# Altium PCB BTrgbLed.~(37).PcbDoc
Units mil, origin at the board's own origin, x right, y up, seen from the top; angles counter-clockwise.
Board outline 3886.28 x 3884.79 mil, 2 copper layers (Top Layer, Bottom Layer); 13 components, 12 nets, 62 pads, 7 vias.
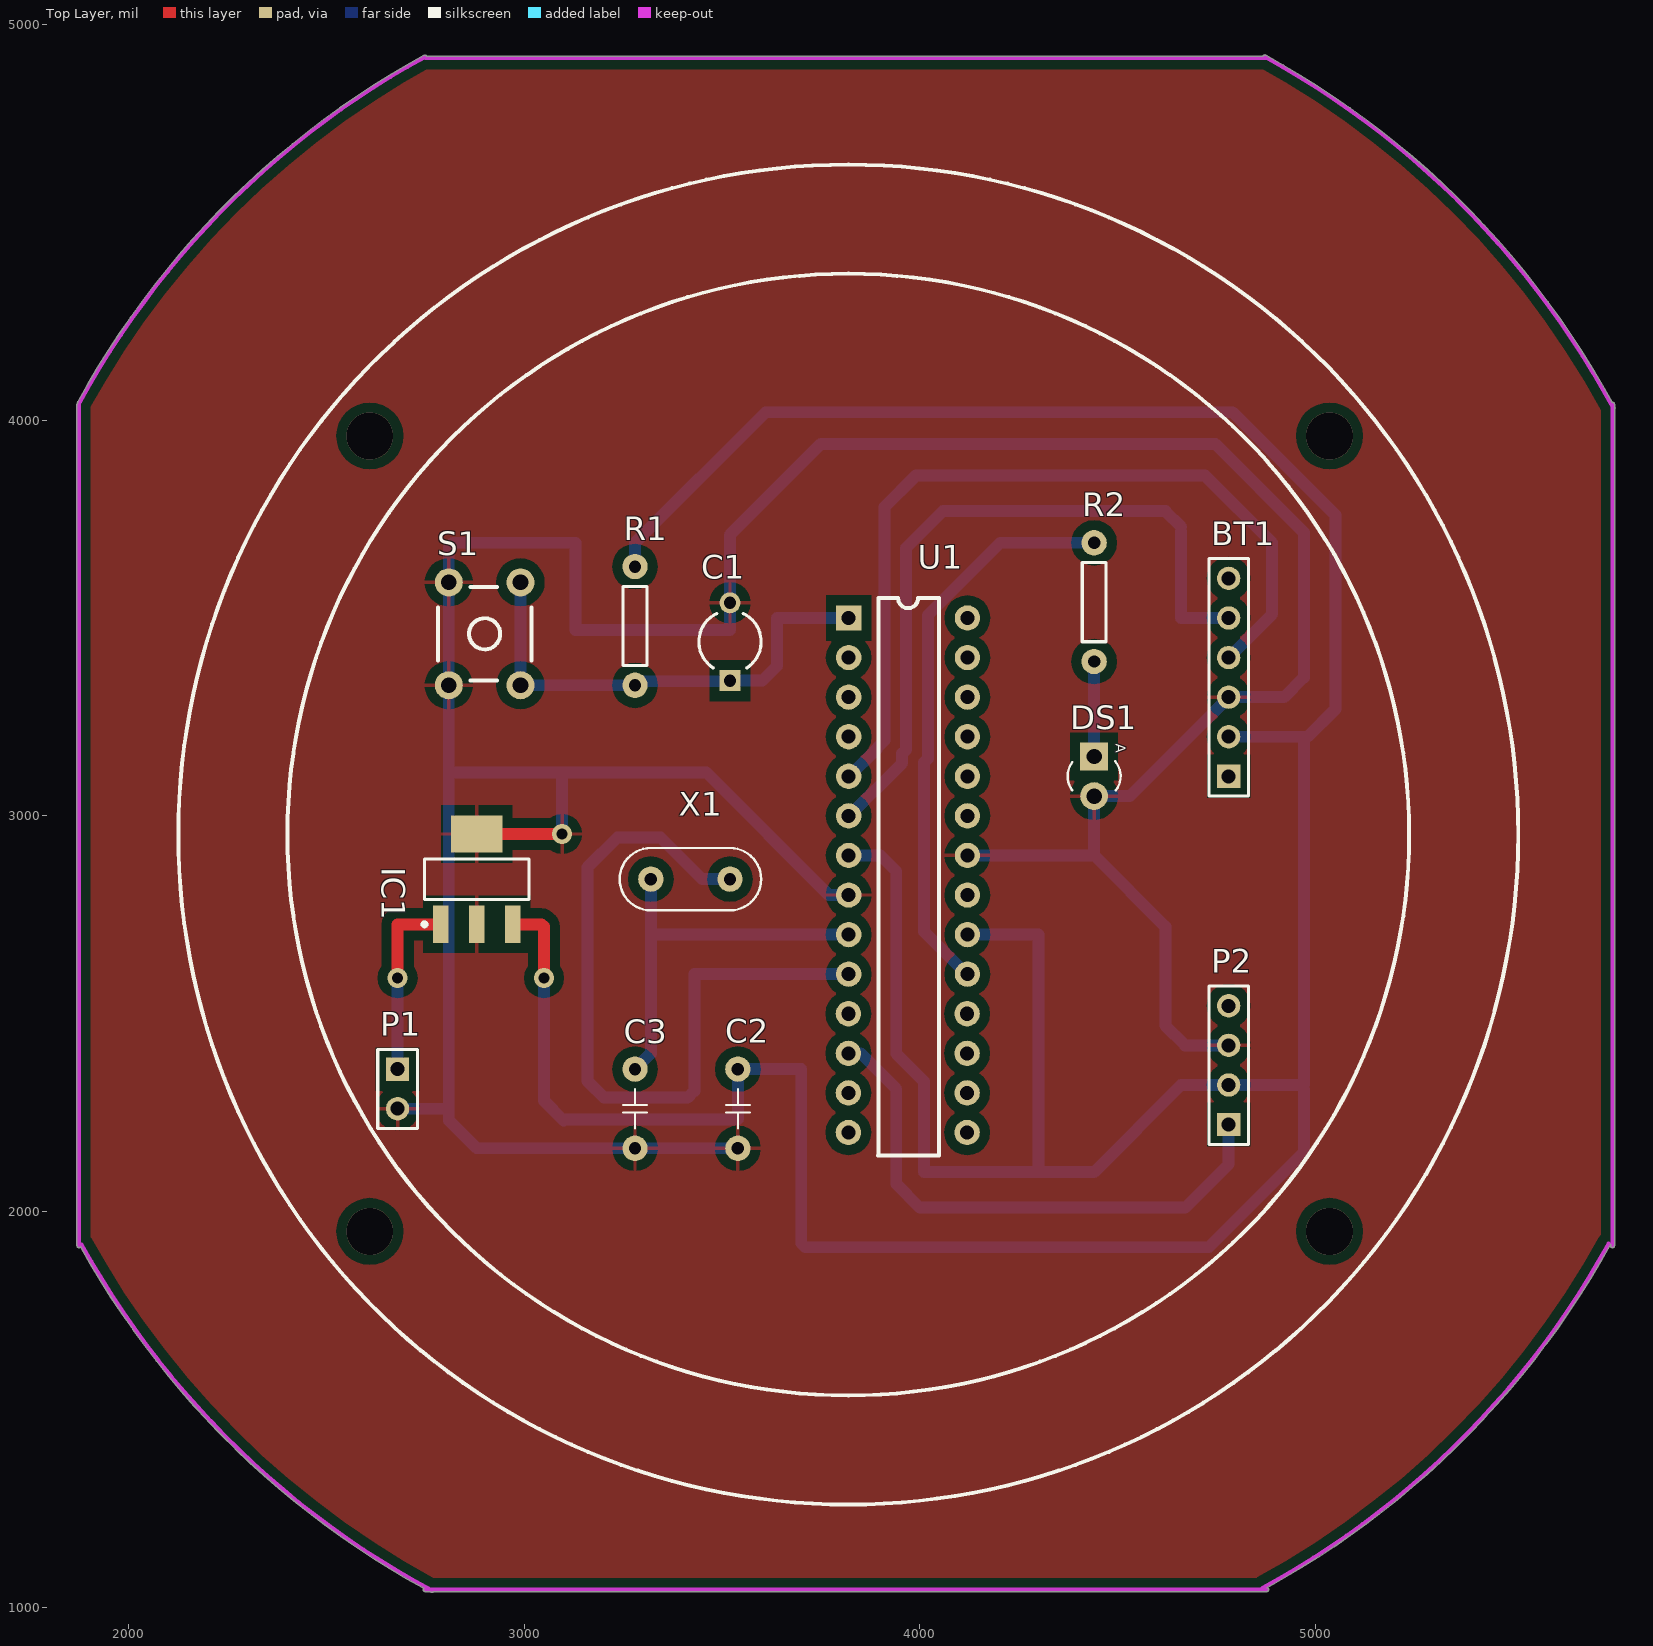
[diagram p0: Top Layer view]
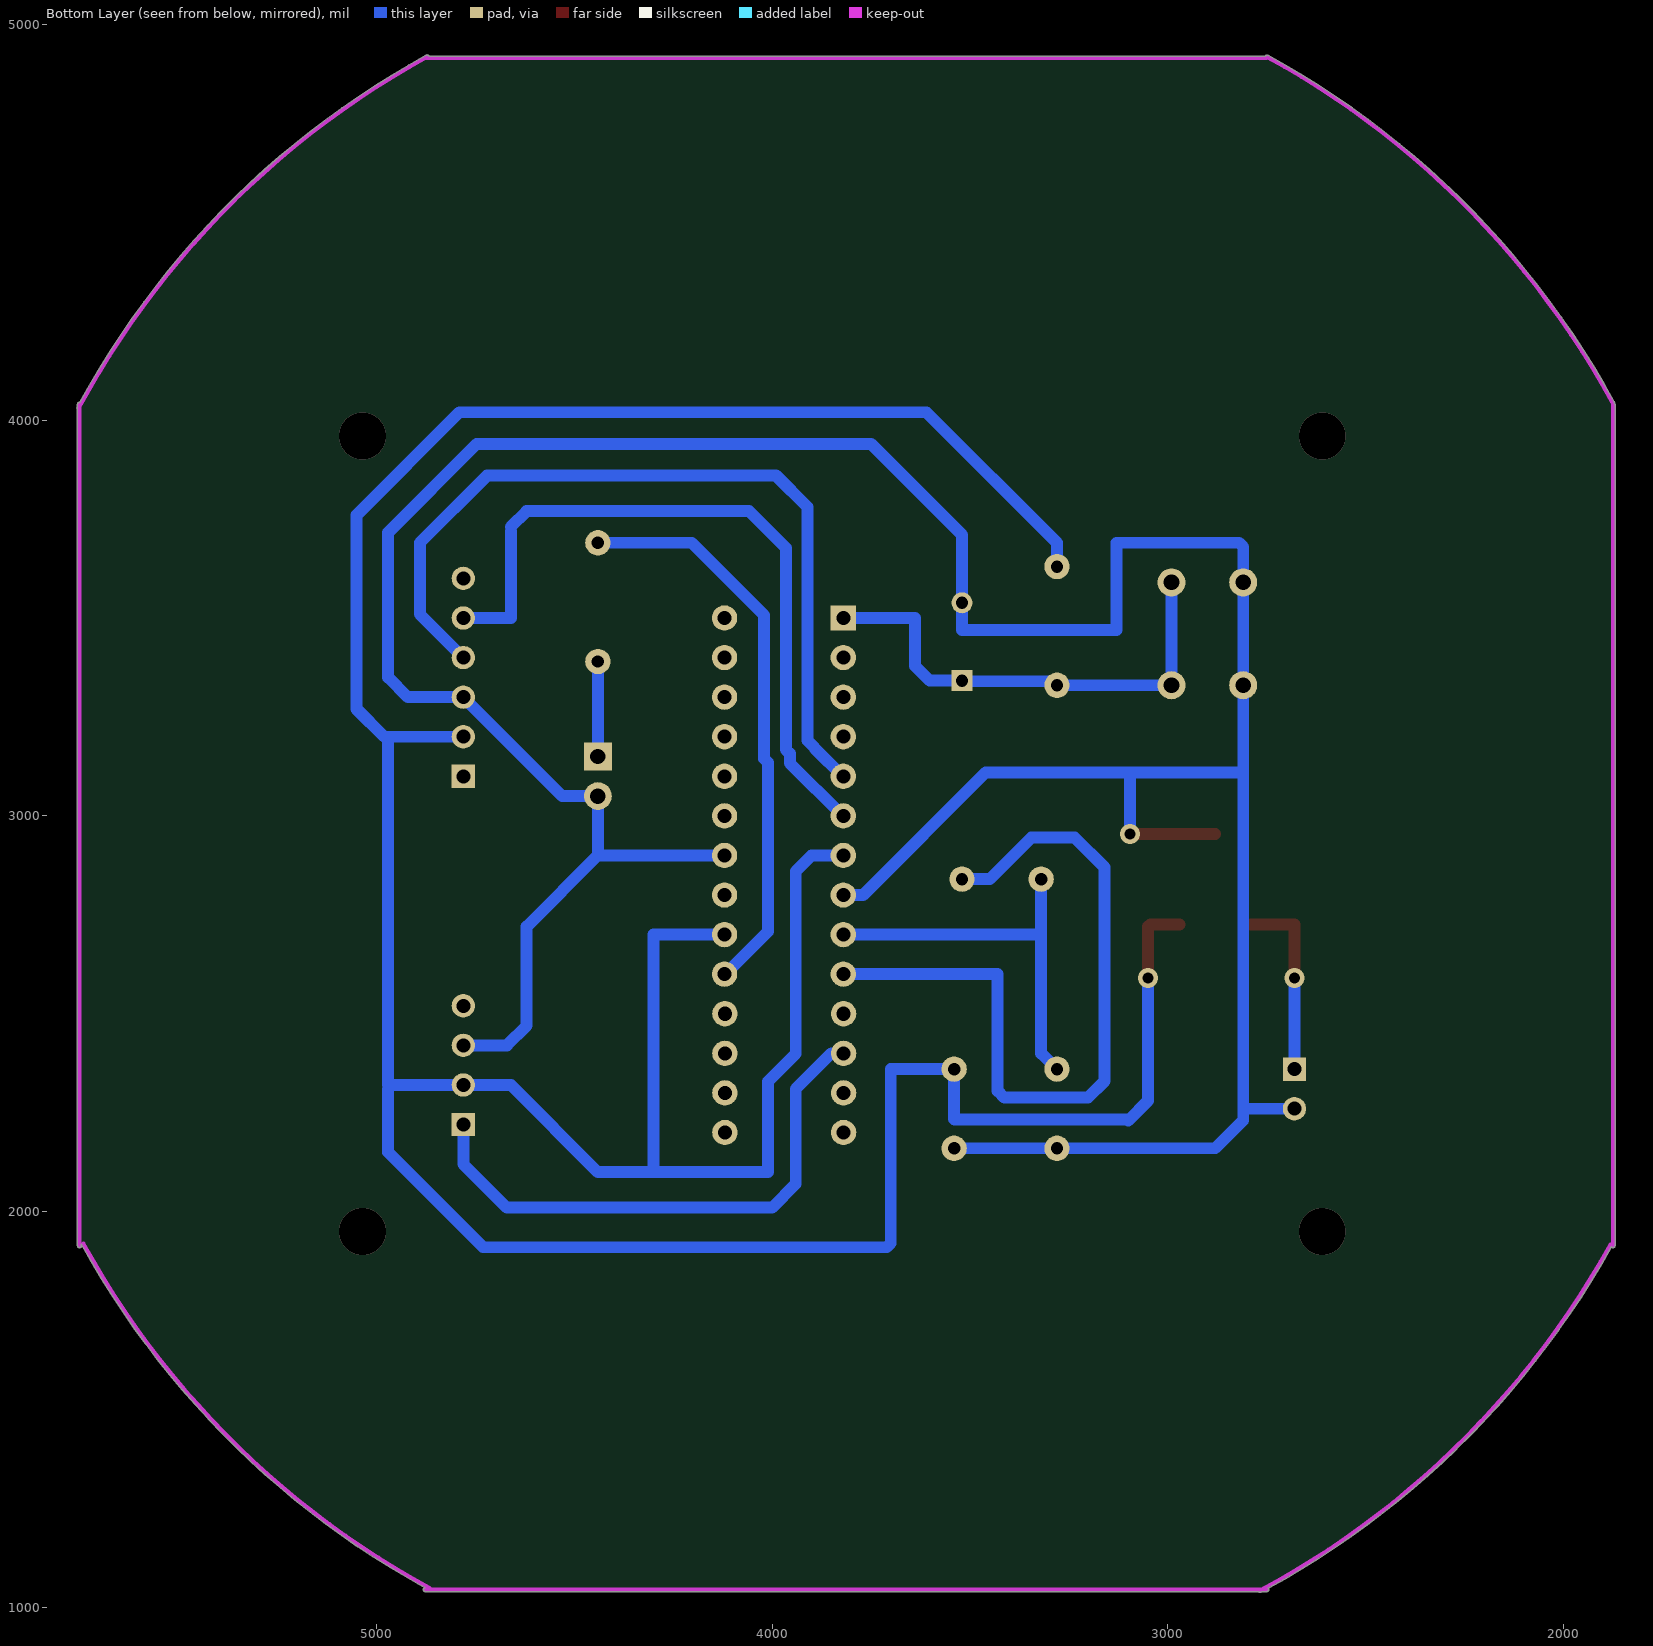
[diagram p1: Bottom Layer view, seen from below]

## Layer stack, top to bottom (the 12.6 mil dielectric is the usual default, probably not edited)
Top Layer: signal copper 1.4
Dielectric: dielectric 12.6, FR-4, Dk 4.8
Bottom Layer: signal copper 1.4

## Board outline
2750,1039.98 2761.53,1039.98 ccw(c3810.28,2985) 2764.5,1038.38 ccw(c2766.88,1042.8) 2771.03,1039.98 4875.98,1039.98 ccw(c4875.98,1045) 4881,1045 ccw(c4875.98,1045) 4877.16,1049.88 ccw(c3810.28,2985) 5744.74,1916.92 ccw(c5740.35,1919.34) 5744.98,1917.43 5744.98,1914.02 ccw(c5750,1914.02) 5755.02,1914.02 5755.02,4027.36 ccw(c5751.25,4030.67) 5756.26,4030.67 ccw(c5751.25,4030.67) 5755.66,4033.05 ccw(c3810.28,2985) 5755.02,4034.26 5755.02,4040 ccw(c5750,4040) 5749.21,4044.95 ccw(c3810.28,2985) 4873.82,4921.96 ccw(c4871.41,4917.56) 4867.03,4920.02 2752.96,4920.02 ccw(c2748.72,4917.33) 2746.3,4921.73 ccw(c3810.28,2985) 1872.41,4046.9 ccw(c1876.81,4044.49) 1871.83,4043.89 ccw(c1875,4040) 1869.98,4040 1869.98,1914.02 ccw(c1875,1914.02) 1879.06,1911.07 ccw(c3810.28,2985) 2746.23,1048.31 ccw(c2750,1045)

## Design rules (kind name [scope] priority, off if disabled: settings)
Clearance 舖銅安全間距 [All] p1: gap=25
Clearance [All] p2: gap=10
PolygonConnect [All] p1: connectstyle=Relief reliefconductorwidth=10 reliefentries=4 polygonreliefangle="90 Angle"
RoutingLayers [All] p1: top layer_v5=FALSE bottom layer_v5=TRUE
RoutingVias [All] p1: holewidth=28 width=50 viastyle="Through Hole" minholewidth=28 minwidth=50 maxholewidth=28 maxwidth=50
SilkscreenOverComponentPads [All] p1: minsilkscreentomaskgap=10
SolderMaskExpansion [All] p1: expansion=4
Width [All] p1: maxlimit=40 minlimit=20 preferedwidth=30
26 further rules are at their usual default settings.

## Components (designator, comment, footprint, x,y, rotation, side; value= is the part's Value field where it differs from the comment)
BT1 "Bluetooth" Bluetooth 4780,3100 r90 top
C1 "47uF" CAPR5-4X5 3520,3440 r90 top
C2 "22pF" C200 3540,2260 r0 top
C3 "22pF" C200 3280,2260 r180 top
DS1 "TX-LED" LED-3mm_G 4440,3100 r270 top
IC1 "AM1117-5V" SOT-223 2880,2840 r90 top
P1 "12V" HDR1X2 2680,2360 r270 top
P2 "環形LED燈" HDR1X4 4780,2220 r90 top
R1 "10k" AXIAL-0.3 3280,3480 r270 top
R2 "220" AXIAL-0.3 4440,3540 r90 top
S1 "SW-PB" TACK6 2900,3460 r90 top
U1 "ATmega328" DIP-28 3820,3500 r270 top
X1 "16MHz" XTAL4-8 3420,2840 r0 top

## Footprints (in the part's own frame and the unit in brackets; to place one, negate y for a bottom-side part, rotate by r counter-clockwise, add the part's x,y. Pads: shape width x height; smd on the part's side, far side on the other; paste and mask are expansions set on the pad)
AXIAL-0.3 [mil] "0.3\" Resistor; 2 Leads"
  round 64 hole 31.5: 1(-150,0) 2(150,0)
  silkscreen extent -100,-30 100,30, body extent -161,-39 165,39, height 86
Bluetooth [mm]
  rect 1.5x1.5 hole 0.9: 1(0,0)
  round 1.5 hole 0.9: 2(2.54,0) 3(5.08,0) 4(7.62,0) 5(10.16,0) 6(12.7,0)
  silkscreen extent -1.27,-1.27 13.97,1.27, body extent -1.25,-1.3 13.97,1.28, height 11
C200 [mil] "塑膠電容器"
  round 64 hole 31.5: 1(0,100) 2(0,-100)
  silkscreen extent -30,-50 30,50, body extent -41,-136 39,135, height 354
CAPR5-4X5 [mm] "Capacitor; 2 Leads"
  rect 1.35x1.35 hole 0.8: 1(-2.5,0)
  round 1.35 hole 0.8: 2(2.5,0)
  silkscreen extent -1.69,-2 1.82,2
DIP-28 [mil]
  rect 64x64 hole 35.43: 1(0,0)
  round 64 hole 35.43: 2(100,0) 3(200,0) 4(300,0) 5(400,0) 6(500,0) 7(600,0) 8(700,0) 9(800,0) 10(900,0) 11(1000,-0.79) 12(1100,-0.79) 13(1200,-0.79) 14(1300,-0.79) 15(1300,299.21) 16(1200,299.21) 17(1100,299.21) 18(1000,299.21) 19(900,300) 20(800,300) 21(700,300) 22(600,300) 23(500,300) 24(400,300) 25(300,300) 26(200,300) 27(100,300) 28(0,300)
  silkscreen extent -50,74 1358,228, body extent -53,-5 1358,304, height 209
HDR1X2 [mm] "Connector; Header; 2 Position"
  rect 1.5x1.5 hole 0.9: 1(0,0)
  round 1.5 hole 0.9: 2(2.54,0)
  silkscreen extent -1.27,-1.27 3.81,1.27
HDR1X4 [mm] "Connector; Header; 4 Position"
  rect 1.5x1.5 hole 0.9: 1(0,0)
  round 1.5 hole 0.9: 2(2.54,0) 3(5.08,0) 4(7.62,0)
  silkscreen extent -1.27,-1.27 8.89,1.27
LED-3mm_G [mil] "3mm LED_Green"
  rect 70x70 hole 39: 1(-50,0)
  round 70 hole 39: 2(50,0)
  silkscreen extent -38,-67 35,67, body extent -66,-68 67,66, height 181
SOT-223 [mm] "SOT223, 4-Leads, Body 6.7x7.3mm (max), Pitch 2.30mm, IPC Medium Density"
  rect 2.4x1 smd: 1(-2.9,2.3) 2(-2.9,0) 3(-2.9,-2.3)
  rect 2.4x3.3 smd: 2(2.9,0)
  silkscreen extent -3.02,-3.35 1.3,3.47, body extent -1.86,-3.35 1.86,3.35, height 1.8
TACK6 [mm]
  round 1.8 hole 1: 1(-3.3,2.3) 1(3.3,2.3) 2(-3.3,-2.3) 2(3.3,-2.3)
  silkscreen extent -3,-3 3,3, body extent -3,-3.01 3.08,3.04, height 8
XTAL4-8 [mil]
  round 64 hole 31.5: 1(-100,0) 2(100,0)
  silkscreen extent -179,-79 179,79, body extent -178,-80 192,79, height 157

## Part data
C1: library part "Cap Pol1", "Polarized Capacitor (Radial)"
C2 C3: library part Cap, "Capacitor"
DS1: library part LED, "Typical INFRARED GaAs LED"
IC1: library part AM1117
P1: library part "Header 2", "Header, 2-Pin"
P2: library part "Header 4", "Header, 4-Pin"
R1 R2: library part Res, "Resistor"
S1: "Switch"
U1: "Arduino"
X1: library part XTAL, "Crystal Oscillator"

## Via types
v1: diameter 118.11, hole 118.11, Top Layer to Bottom Layer, 4 vias
v2: diameter 50, hole 28, Top Layer to Bottom Layer, 3 vias

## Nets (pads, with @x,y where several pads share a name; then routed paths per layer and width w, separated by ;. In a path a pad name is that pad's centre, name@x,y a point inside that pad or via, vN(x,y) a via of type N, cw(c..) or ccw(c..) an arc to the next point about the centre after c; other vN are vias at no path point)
DI: P2.1 U1.12 | length 1408.5
  Bottom Layer w30: U1.12 3850,2400 3940,2310 3940,2070 4000,2010 4670,2010 4780,2120 P2.1
DO: P2.4
GND: BT1.3 C1.2 C2.2 C3.1 DS1.2 IC1.2 P1.2 P2.3 S1.1 U1.8 U1.22 | length 8812.8
  Top Layer w30: IC1.2@2880,2954.17 v2(3095.83,2954.17)
  Bottom Layer w30: P1.2 2804.45,2260 ; S1.1@2809.45,3580.49 2809.45,3330.08 2809.45,2230.55 2880,2160 C3.1 C2.2 ; S1.1@2809.45,3589.92 2809.45,3679.45 2820,3690 3130,3690 3130,3470 3520,3470 C1.2 3520,3710 3750,3940 4746,3940 4970,3716 4970,3350 4920,3300 BT1.3 4530,3050 DS1.2 4440,2900 ; 2819.45,3110 3095.83,3110 ; v2(3095.83,2954.17) 3095.83,3110 ; U1.8 3770,2800 3460,3110 3095.83,3110 ; U1.22 4440,2900 ; P2.3 4670,2420 4620,2470 4620,2720 4440,2900
NetC1_1: C1.1 R1.2 S1.2 U1.1 | length 1214.5
  Bottom Layer w30: S1.2@2990.55,3320.65 S1.2@2990.55,3330.08 ; S1.2@2990.55,3580.49 S1.2@2990.55,3330.08 ; R1.2@3279.92,3330.08 S1.2@2990.55,3330.08 ; R1.2@3280,3340 C1.1@3508.43,3340 ; C1.1 3601.57,3341.57 3638.43,3378.43 3638.43,3500 U1.1
NetC2_2: U1.10 X1.2 | length 1954
  Bottom Layer w30: X1.2 3450,2840 3345,2945 3235,2945 3160,2870 3160,2330 3202,2288 3413,2288 3430,2305 3430,2600 U1.10
NetC3_2: C3.2 U1.9 X1.1 | length 991.6
  Bottom Layer w30: C3.2 3320,2400 X1.1 ; 3325,2700 U1.9
NetDS1_1: DS1.1 R2.1 | length 240
  Bottom Layer w30: DS1.1 R2.1
NetIC1_1: IC1.1 P1.1 | length 469.4
  Top Layer w30: v2(2680,2590) 2680,2720 ; 2680,2725.83 IC1.1
  Bottom Layer w30: P1.1 v2(2680,2590)
NetR2_2: R2.2 U1.19 | length 1453.6
  Bottom Layer w30: U1.19 4118.18,2600 4010,2708.18 4010,3134.44 4020,3144.44 4020,3507 4203,3690 R2.2
RX: BT1.5 U1.6 | length 1828.2
  Bottom Layer w30: U1.6 3821.82,3000 3955,3133.18 3955,3157.22 3965,3167.22 3965,3677 4058,3770 4620,3770 4660,3730 ; 4660,3720 4660,3500 BT1.5
TX: BT1.4 U1.5 | length 2137.5
  Bottom Layer w30: U1.5 3821.82,3100 3892,3170.18 3892,3172 3910,3190 3910,3780 3990,3860 4720,3860 4890,3690 4890,3510 BT1.4
VCC: BT1.2 C2.1 IC1.3 P2.2 R1.1 U1.7 U1.20 | length 9775.6
  Top Layer w30: IC1.3 3044.17,2725.83 ; v2(3050,2590) 3050,2720
  Bottom Layer w30: v2(3050,2590) 3050,2280 3100,2230 3103,2233 3539,2233 3540,2234 C2.1 3700,2360 3700,1920 3710,1910 4730,1910 4970,2150 4970,2310 ; R1.1 3280,3690 3610,4020 4790,4020 5050,3760 5050,3270 4980,3200 BT1.2 ; U1.7 3900,2900 3940,2860 3940,2399 4010,2329 4010,2100 4300,2100 ; U1.20 4300,2700 4300,2100 ; 4970,3190 4970,2320 P2.2 4660,2320 4440,2100 4300,2100
pads on no net: BT1.1 BT1.6 U1.2 U1.3 U1.4 U1.11 U1.13 U1.14 U1.15 U1.16 U1.17 U1.18 U1.21 U1.23 U1.24 U1.25 U1.26 U1.27 U1.28
copper on no net:
  other v1: 2610,1950 5035,1950 2610,3960 5035,3960

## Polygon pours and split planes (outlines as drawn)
GND on Top Layer "Top Layer-No Net" (solid): 1873.98,1914.02 1875.81,1913.41 1875.82,1913.42 1882.55,1913.01 ccw(c3810.28,2985) 2748.16,1051.82 2750.17,1049 4873.26,1049 4875.23,1053.38 ccw(c3810.28,2985) 5741.24,1918.85 5741.24,1918.86 5741.29,1918.96 5748.98,1917.43 5748.98,1914.02 5751.02,1914.02 5751.02,4027.36 5752.01,4030 5752.02,4030.01 5752.26,4030.67 5752.14,4031.15 5751.49,4032.36 5751.02,4034.26 5751.02,4040 5749.85,4041 5749.84,4041 5745.7,4043.03 ccw(c3810.28,2985) 4871.9,4918.45 4871.89,4918.46 4870.52,4918.06 4867.03,4916.02 2752.96,4916.02 2749.58,4917.88 2749.57,4917.89 2748.23,4918.22 ccw(c3810.28,2985) 1875.92,4044.98 1875.91,4044.97 1875.8,4044.38 1875.8,4044.37 1875.83,4043.89 1874.36,4040.79 1874.35,4040.78 1873.98,4040

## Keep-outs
Keep-Out Layer:
  lines w10: 1875,1914.02 1875,4040 ; 1876.81,4044.49 cw(c3810.28,2985) 2748.72,4917.33 ; 1881.24,1917.47 ccw(c3810.28,2985) 2766.88,1042.8 ; 2750,1045 4875.98,1045 ; 2750,4915 4875.98,4915 ; 4865.51,1049.21 ccw(c3810.28,2985) 5740.35,1919.34 ; 4871.41,4917.56 cw(c3810.28,2985) 5751.25,4030.67 ; 5750,1914.02 5750,4040

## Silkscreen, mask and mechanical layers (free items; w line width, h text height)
Top Overlay:
  circle w10: c3818.9,2952.76 r1417.32
  circle w10: c3818.9,2952.76 r1692.91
